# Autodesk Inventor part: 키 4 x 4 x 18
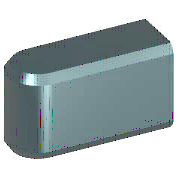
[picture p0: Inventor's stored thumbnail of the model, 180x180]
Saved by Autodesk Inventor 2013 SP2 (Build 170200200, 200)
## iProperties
IsCustomPart: 1
Created: 2012-02
Part Number: 키 4 x 4 x 18
Material: 강철, 연강
Description: 키 및 해당 키홈
Document SubType Name: Modeling
Standard: KS B 1311
Designer: mduedu
Standards Organization: KS
Language: ko-KR
Size Designation: 4 x 4 x 18
Categories: <MemberInstance><Categories><Category DisplayName="샤프트 부품" InternalName="7f7aeb1f-a693-4053-b835-cee3144e0d98" Mnemonic="SHFT"><Category DisplayName="키" Interna
Density: 1 g/cm^3
Author: mduedu
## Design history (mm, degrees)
sketch "스케치1"
  geometry: L1 (2, 2)-(18, 2); L2 (18, 2)-(18, -2); L3 (18, -2)-(2, -2); L4 (0, 7)-(0, -7) reference; L5 (-5, 0)-(30, 0) reference; A1 r 2 centre (2, 0) between (2, 2) and (2, -2)
  constraints: 6 end point, 3 tangent, 2 point on circle, 1 centre point, 1 horizontal, 1 parallel, 1 perpendicular, 1 point on line
  dimensions: "d0" = 2 radius of A1 (= 0.5 x PB); "d7" = 18 distance between parallel lines of L2 L4 (= NLG)
workplane "Work Plane1"
workplane "Work Plane2"
extrude "본체1" new body sketch "스케치1" taper "d3" = 0 deg; stored distance "d4" = 10
workaxis "Work Axis1"
workplane "Work Plane4"
body "Solid1"
chamfer "모따기1" distance "d8" = 0.25 (= PHH); stored, may be unused: second distance "d9" = 0.25 (= PHH), angle "d13" = 45 deg
other parameters: "d1" = -2.5 (= -PNT), "d2" = 1.5 (= PH - PNT), "NLG" = 18 [user parameter; used in 2 equation terms], "PB" = 4 [user parameter; used in 1 equation term], "PNT" = 2.5 [user parameter; used in 2 equation terms], "PH" = 4 [user parameter; used in 1 equation term], "PHH" = 0.25 [user parameter; used in 2 equation terms], "d10" = 0, "d16" = 0, "d17" = 0, "d18" = 0, "RR" = 0.08 [user parameter], "WDMAX" = 12 [user parameter], "PLB1" = 18 (= NLG) [user parameter], "PUEB" = 1.8 [user parameter]
